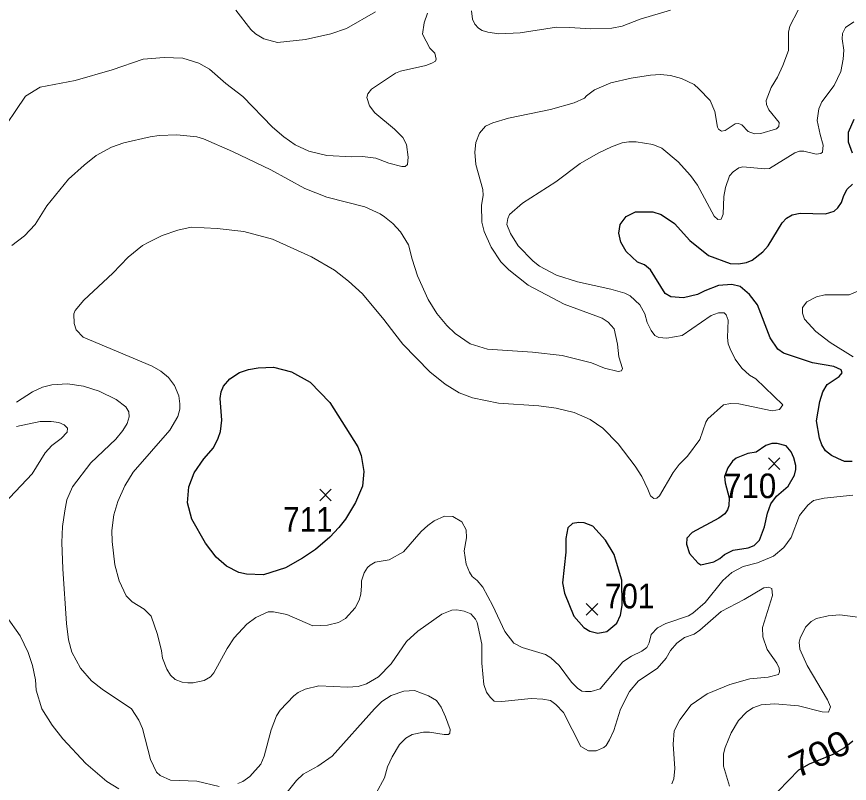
# Model space of a CAD drawing. Extents: x 294.2 to 320.3, y 7482.7 to 7510.7.
# Drawn here: x 302.381 to 305.089, y 7505.286 to 7507.777 of the extents above; entities that cross this region are included whole.
import ezdxf
from ezdxf.enums import TextEntityAlignment as Align

# ---------------------------------------------------------------- set-up
doc = ezdxf.new("R2010")
doc.units = 0
doc.header["$LTSCALE"] = 0.032
for name, color, linetype, lineweight in [('1', 7, 'Continuous', 25), ('2', 7, 'Continuous', 13), ('21', 7, 'Continuous', 25)]:
    doc.layers.add(name, color=color, linetype=linetype, lineweight=lineweight)
doc.layers.add('61', color=7, linetype='Continuous')

msp = doc.modelspace()

# ---------------------------------------------------------------- linework, layer by layer
at = {"layer": '1'}
for points in [[(305.099, 7507.3337), (305.0861, 7507.3695), (305.0861, 7507.4026), (305.1039, 7507.4448)], [(304.707, 7506.9073), (304.6637, 7506.9034), (304.6189, 7506.8868), (304.5949, 7506.8742), (304.5493, 7506.864), (304.5084, 7506.8671), (304.4903, 7506.8782), (304.4419, 7506.9553), (304.4231, 7506.971), (304.4003, 7506.9796), (304.3627, 7507.0146), (304.3454, 7507.0445), (304.3391, 7507.0736), (304.343, 7507.1019), (304.3635, 7507.1286), (304.3938, 7507.1435), (304.4496, 7507.1428), (304.4763, 7507.1349), (304.5199, 7507.1058), (304.5695, 7507.05), (304.6312, 7507.0012), (304.7012, 7506.9752), (304.7287, 7506.9744), (304.7543, 7506.9783), (304.7731, 7506.9862), (304.8077, 7507.0129), (304.8242, 7507.0326), (304.8702, 7507.1073), (304.8844, 7507.123), (304.9025, 7507.134), (304.9292, 7507.1387), (305.0106, 7507.1364), (305.0389, 7507.145), (305.0515, 7507.156), (305.0632, 7507.1741), (305.0703, 7507.1961), (305.0821, 7507.2166), (305.0986, 7507.2331)], [(304.8745, 7506.684), (304.8556, 7506.6966), (304.8312, 7506.7335), (304.7899, 7506.8413), (304.764, 7506.8751), (304.7333, 7506.901), (304.707, 7506.9073)], [(305.0976, 7506.3316), (305.0732, 7506.3324), (305.0512, 7506.3418), (305.0304, 7506.3512), (305.0115, 7506.3662), (304.9997, 7506.3866), (304.9911, 7506.4078), (304.9816, 7506.4645), (304.9923, 7506.5266), (305.0025, 7506.558), (305.0166, 7506.5824), (305.0552, 7506.6083), (305.0654, 7506.6201), (305.0619, 7506.6303), (305.0383, 7506.6405), (304.9691, 7506.6531), (304.8745, 7506.684)], [(304.8567, 7505.261), (304.9246, 7505.3302), (304.9594, 7505.3499), (305.0364, 7505.3805), (305.072, 7505.4017), (305.0995, 7505.424)]]:
    msp.add_lwpolyline(points, dxfattribs=at)
for points in [[(302.9901, 7506.3406), (303.0208, 7506.3767), (303.0369, 7506.4082), (303.0439, 7506.4295), (303.0479, 7506.4664), (303.0426, 7506.5372), (303.0461, 7506.5586), (303.054, 7506.5767), (303.0744, 7506.601), (303.1055, 7506.6207), (303.1354, 7506.6309), (303.1668, 7506.6364), (303.2166, 7506.6388), (303.2749, 7506.6237), (303.3358, 7506.5901), (303.3993, 7506.5242), (303.4905, 7506.3801), (303.5015, 7506.3518), (303.5097, 7506.2994), (303.5052, 7506.2518), (303.4832, 7506.1983), (303.4502, 7506.1448), (303.4292, 7506.1173), (303.3993, 7506.0858), (303.3529, 7506.0465), (303.3104, 7506.0174), (303.2549, 7505.9867), (303.1836, 7505.9639), (303.1285, 7505.9655), (303.1036, 7505.9718), (303.0634, 7505.9916), (303.0295, 7506.0216), (302.9951, 7506.067), (302.951, 7506.1448), (302.937, 7506.1972), (302.9414, 7506.2496), (302.9587, 7506.2955)], [(304.8543, 7506.3906), (304.8368, 7506.3906), (304.8171, 7506.3843), (304.7857, 7506.3623), (304.7589, 7506.3584), (304.7208, 7506.3426), (304.7082, 7506.3332), (304.6941, 7506.3119), (304.6831, 7506.2836), (304.6854, 7506.263), (304.698, 7506.2142), (304.6969, 7506.1878), (304.6922, 7506.1752), (304.6835, 7506.1619), (304.6638, 7506.1477), (304.5779, 7506.1013), (304.5606, 7506.0824), (304.559, 7506.0636), (304.5689, 7506.0331), (304.5957, 7506.0031), (304.6059, 7505.9967), (304.6477, 7506.0062), (304.6674, 7506.0164), (304.6823, 7506.0298), (304.7113, 7506.044), (304.7598, 7506.0516), (304.779, 7506.0593), (304.7962, 7506.0765), (304.8128, 7506.1193), (304.8224, 7506.164), (304.8332, 7506.1947), (304.8517, 7506.2195), (304.8894, 7506.2514), (304.9098, 7506.2879), (304.9143, 7506.3058), (304.915, 7506.3185), (304.9086, 7506.3434), (304.899, 7506.3632), (304.883, 7506.383)], [(304.332, 7506.0043), (304.3236, 7506.0295), (304.2959, 7506.0767), (304.2543, 7506.1215), (304.2268, 7506.1325), (304.2087, 7506.1333), (304.1882, 7506.1301), (304.1733, 7506.1168), (304.167, 7506.0822), (304.167, 7506.0374), (304.1558, 7505.9374), (304.1629, 7505.9044), (304.1923, 7505.8289), (304.2249, 7505.7927), (304.2446, 7505.7809), (304.2713, 7505.7746), (304.2996, 7505.7801), (304.3327, 7505.8069), (304.3447, 7505.8328), (304.3498, 7505.8643), (304.3491, 7505.9469)]]:
    msp.add_lwpolyline(points, close=True, dxfattribs=at)
at = {"layer": '2'}
for points in [[(302.9734, 7507.6268), (303.0079, 7507.607), (303.0608, 7507.5597), (303.117, 7507.5175), (303.2134, 7507.4179), (303.2498, 7507.3867), (303.2862, 7507.3605), (303.3309, 7507.3401), (303.3897, 7507.326), (303.4714, 7507.3222), (303.5059, 7507.3235), (303.5493, 7507.3171), (303.5914, 7507.3017), (303.6336, 7507.2909), (303.6444, 7507.2909), (303.6521, 7507.2966), (303.6539, 7507.3209), (303.6482, 7507.3624), (303.6367, 7507.3848), (303.6099, 7507.4122), (303.5454, 7507.4652), (303.5282, 7507.4882), (303.5199, 7507.515), (303.5231, 7507.5271), (303.5346, 7507.5418), (303.6131, 7507.5936), (303.6297, 7507.6), (303.7115, 7507.6191), (303.7314, 7507.626), (303.7427, 7507.6331), (303.7453, 7507.6389), (303.7408, 7507.6587), (303.7249, 7507.6746), (303.7006, 7507.7206), (303.7057, 7507.7577), (303.7172, 7507.7883)], [(303.548, 7507.7928), (303.4535, 7507.7385), (303.4024, 7507.7213), (303.3207, 7507.7027), (303.2288, 7507.6938), (303.1853, 7507.7053), (303.1579, 7507.7219), (303.1426, 7507.7359), (303.0934, 7507.7985)], [(304.507, 7507.7985), (304.4087, 7507.7691), (304.3499, 7507.7461), (304.3167, 7507.7397), (304.2478, 7507.7379), (304.1788, 7507.7423), (304.1367, 7507.7436), (304.0179, 7507.7244), (303.949, 7507.7219), (303.9132, 7507.727), (303.8953, 7507.7321), (303.8825, 7507.7397), (303.871, 7507.7526), (303.8628, 7507.7692), (303.8602, 7507.796)], [(304.2272, 7507.5125), (304.2335, 7507.5203), (304.2605, 7507.5392), (304.3134, 7507.5626), (304.3793, 7507.5776), (304.4419, 7507.5878), (304.4751, 7507.5897), (304.507, 7507.5859), (304.5428, 7507.577), (304.5836, 7507.5571), (304.5996, 7507.5431), (304.6366, 7507.5048), (304.6512, 7507.4691), (304.6596, 7507.418), (304.663, 7507.4116), (304.673, 7507.4052), (304.6851, 7507.4071), (304.7177, 7507.4288), (304.7278, 7507.4301), (304.7388, 7507.4263), (304.7598, 7507.4045), (304.7803, 7507.3962), (304.8006, 7507.3981), (304.8516, 7507.4131), (304.8593, 7507.4207), (304.86, 7507.4338), (304.8269, 7507.4742), (304.8198, 7507.4921), (304.8185, 7507.5048), (304.8341, 7507.5474), (304.8547, 7507.5813), (304.8725, 7507.6189), (304.8903, 7507.6673), (304.8913, 7507.727), (304.8951, 7507.7462), (304.9226, 7507.7985)], [(305.1033, 7507.7608), (305.0765, 7507.7417), (305.0663, 7507.7232), (305.065, 7507.7053), (305.0708, 7507.6683), (305.0688, 7507.6389), (305.0612, 7507.5993), (305.0395, 7507.5533), (304.9993, 7507.5003), (304.989, 7507.478), (304.9839, 7507.4397), (304.9935, 7507.395), (305.0031, 7507.3599)], [(302.4575, 7507.5482), (302.5711, 7507.5699), (302.6912, 7507.6044), (302.7921, 7507.6389), (302.861, 7507.6452), (302.921, 7507.6427), (302.9734, 7507.6268)], [(302.317, 7507.3829), (302.4096, 7507.5195), (302.4575, 7507.5482)], [(303.8858, 7507.3988), (303.9055, 7507.4218), (303.9298, 7507.4327), (303.9809, 7507.448), (304.1175, 7507.4761), (304.1941, 7507.4971), (304.2272, 7507.5125)], [(302.3652, 7507.034), (302.4066, 7507.0652), (302.4416, 7507.1017), (302.4798, 7507.1626), (302.5501, 7507.2494), (302.6005, 7507.2954), (302.6394, 7507.326), (302.6899, 7507.3535), (302.7295, 7507.3675), (302.815, 7507.3867), (302.8444, 7507.3911), (302.9019, 7507.3937), (302.967, 7507.3867), (302.9887, 7507.3809), (303.0832, 7507.3388), (303.2071, 7507.28), (303.3182, 7507.2194), (303.3897, 7507.1906), (303.5135, 7507.1594), (303.5633, 7507.1364), (303.5773, 7507.1268), (303.6041, 7507.1051), (303.6297, 7507.0783), (303.6552, 7507.0355), (303.6667, 7506.9889), (303.6846, 7506.9353), (303.7191, 7506.8587), (303.7478, 7506.8127), (303.7798, 7506.7738), (303.8066, 7506.7482), (303.8557, 7506.7143), (303.9119, 7506.6965), (304.0588, 7506.6875), (304.1546, 7506.676), (304.2503, 7506.6525), (304.2925, 7506.6358), (304.3372, 7506.6244), (304.3474, 7506.6269), (304.3506, 7506.6339), (304.3391, 7506.6722), (304.3346, 7506.7131), (304.3237, 7506.7629), (304.3048, 7506.7844), (304.2853, 7506.7972), (304.1618, 7506.8432), (304.0447, 7506.9046), (303.9815, 7506.9551), (303.956, 7506.9813), (303.9241, 7507.0285), (303.9017, 7507.0796), (303.894, 7507.1102), (303.8927, 7507.1652), (303.8978, 7507.1958), (303.8972, 7507.2162), (303.8743, 7507.2967), (303.8704, 7507.3375), (303.8743, 7507.3682), (303.8858, 7507.3988)], [(304.9118, 7507.335), (304.8288, 7507.2845), (304.8135, 7507.2826), (304.7419, 7507.2897), (304.7298, 7507.2858), (304.7107, 7507.2737), (304.6992, 7507.2597), (304.6864, 7507.2226), (304.6806, 7507.1932), (304.6787, 7507.1358), (304.6717, 7507.1191), (304.6615, 7507.1185), (304.6487, 7507.1287), (304.5945, 7507.2303), (304.5721, 7507.2609), (304.5325, 7507.3056), (304.4795, 7507.3503), (304.4495, 7507.3618), (304.3959, 7507.3707), (304.3716, 7507.3707), (304.3499, 7507.3669), (304.3155, 7507.3548), (304.272, 7507.3343), (304.2133, 7507.2999), (304.1348, 7507.2411), (304.0256, 7507.1715), (303.9841, 7507.1351), (303.9783, 7507.1217), (303.9751, 7507.1019), (303.9866, 7507.0732), (304.0115, 7507.033), (304.0607, 7506.9825), (304.0811, 7506.9672), (304.1365, 7506.9377), (304.2043, 7506.9155), (304.3129, 7506.8918), (304.3589, 7506.8785), (304.3755, 7506.8708), (304.4074, 7506.8408), (304.4234, 7506.8114), (304.4316, 7506.7833), (304.4444, 7506.7578), (304.4565, 7506.7418), (304.4687, 7506.7348), (304.4955, 7506.7322), (304.5453, 7506.7418), (304.6398, 7506.8063), (304.6633, 7506.8155), (304.6817, 7506.8155), (304.688, 7506.8089), (304.6943, 7506.791), (304.6926, 7506.7348), (304.6949, 7506.7142), (304.7011, 7506.6978), (304.7177, 7506.6646), (304.7387, 7506.6352), (304.7643, 7506.6122), (304.7841, 7506.6001), (304.8722, 7506.5165), (304.8613, 7506.5011), (304.8377, 7506.4967), (304.7292, 7506.5196), (304.7024, 7506.5209), (304.6793, 7506.5158), (304.6289, 7506.4705), (304.6221, 7506.4602), (304.6025, 7506.404), (304.5623, 7506.3491), (304.5348, 7506.3218), (304.5153, 7506.2962), (304.4712, 7506.2202), (304.4623, 7506.2125), (304.4527, 7506.2119), (304.4425, 7506.2208), (304.4329, 7506.2419), (304.4137, 7506.2828), (304.3927, 7506.3173), (304.3365, 7506.3894), (304.2873, 7506.4398), (304.2458, 7506.4686), (304.1941, 7506.4909), (304.1354, 7506.5049), (304.0792, 7506.5126), (303.948, 7506.5219), (303.8634, 7506.5394), (303.82, 7506.5554), (303.7746, 7506.5835), (303.7248, 7506.6237), (303.6373, 7506.7131), (303.6105, 7506.7463), (303.5755, 7506.7936), (303.5052, 7506.8772), (303.4599, 7506.9181), (303.4145, 7506.9538), (303.3401, 7506.9965)], [(305.0031, 7507.3599), (305.0018, 7507.3375), (304.9961, 7507.333), (304.9813, 7507.3305), (304.9412, 7507.3401), (304.9265, 7507.3407), (304.9118, 7507.335)], [(303.3401, 7506.9965), (303.2132, 7507.0547), (303.1202, 7507.0796), (303.0334, 7507.0892), (302.9491, 7507.0936), (302.9057, 7507.0834), (302.8546, 7507.0662)], [(302.8546, 7507.0662), (302.8112, 7507.0451), (302.7899, 7507.0343), (302.7434, 7506.9964), (302.6937, 7506.9436), (302.5992, 7506.8561), (302.5711, 7506.8229), (302.5667, 7506.8114), (302.5685, 7506.7808), (302.5749, 7506.7597), (302.5979, 7506.7361), (302.8214, 7506.6422), (302.8495, 7506.6256), (302.8744, 7506.6046), (302.8948, 7506.579), (302.9089, 7506.5458), (302.9114, 7506.519), (302.9114, 7506.5024), (302.9051, 7506.4782), (302.8789, 7506.4335), (302.7601, 7506.2968), (302.7327, 7506.2534), (302.7103, 7506.2023), (302.6969, 7506.1589), (302.6911, 7506.1078), (302.6918, 7506.0721), (302.7007, 7505.9967), (302.7141, 7505.9444), (302.7371, 7505.8952), (302.7569, 7505.8761), (302.7959, 7505.8518), (302.8182, 7505.8294), (302.8393, 7505.7694), (302.852, 7505.7171), (302.8559, 7505.6928), (302.8693, 7505.6571), (302.8814, 7505.6379), (302.8961, 7505.6239), (302.9197, 7505.6149), (302.9376, 7505.6123), (302.9555, 7505.6123), (302.9913, 7505.62), (303.011, 7505.6328), (303.0219, 7505.6456), (303.0653, 7505.7248), (303.0883, 7505.7592), (303.1298, 7505.8032), (303.1585, 7505.825), (303.1994, 7505.8435), (303.216, 7505.8435), (303.2594, 7505.8345), (303.3437, 7505.7982), (303.3922, 7505.8), (303.428, 7505.809), (303.4503, 7505.8218), (303.4816, 7505.8563), (303.495, 7505.8818), (303.5007, 7505.901), (303.502, 7505.9278), (303.5027, 7505.9444), (303.5109, 7505.9699), (303.5218, 7505.9871), (303.5307, 7505.9948), (303.5467, 7506.0044), (303.5927, 7506.0127), (303.6387, 7506.0389), (303.6968, 7506.104), (303.7178, 7506.1244), (303.7383, 7506.1391), (303.7728, 7506.1544), (303.7996, 7506.1538), (303.8289, 7506.1359), (303.8423, 7506.1104), (303.8442, 7506.0836), (303.8366, 7506.0414), (303.8429, 7505.998), (303.8532, 7505.9725), (303.8621, 7505.9578), (303.8787, 7505.945), (303.8972, 7505.924), (303.9292, 7505.8627), (303.9688, 7505.7797), (303.9981, 7505.742), (304.0243, 7505.7279), (304.1003, 7505.705), (304.1182, 7505.6941), (304.145, 7505.6692), (304.1852, 7505.6149), (304.2043, 7505.5951), (304.2184, 7505.5855), (304.2312, 7505.5842), (304.2491, 7505.5842), (304.2784, 7505.5938), (304.3525, 7505.6807), (304.3806, 7505.6998)], [(305.1008, 7506.6716), (305.0267, 7506.7182), (304.9801, 7506.7546), (304.943, 7506.7948), (304.936, 7506.814), (304.936, 7506.8325), (304.9507, 7506.851), (304.982, 7506.867), (305.0088, 7506.8734), (305.088, 7506.874), (305.1212, 7506.8874)], [(302.5315, 7505.9827), (302.5284, 7506.0683), (302.5302, 7506.1206), (302.5373, 7506.1717), (302.5443, 7506.2074), (302.5622, 7506.2496), (302.6228, 7506.3275), (302.7039, 7506.4047), (302.7262, 7506.4328), (302.7409, 7506.4552), (302.7467, 7506.4769), (302.746, 7506.4935), (302.7365, 7506.5094), (302.7045, 7506.5337), (302.649, 7506.5605), (302.598, 7506.5764), (302.5469, 7506.5841), (302.4958, 7506.5815), (302.4652, 7506.5733), (302.4326, 7506.5586), (302.3802, 7506.5247)], [(302.3406, 7506.1959), (302.4313, 7506.2917), (302.4734, 7506.36), (302.4958, 7506.3843), (302.5258, 7506.4066), (302.545, 7506.4271), (302.5468, 7506.4404), (302.536, 7506.4513), (302.5188, 7506.4583), (302.4932, 7506.4622), (302.4575, 7506.4615), (302.3809, 7506.4462)], [(304.4917, 7505.8052), (304.5657, 7505.8301), (304.5798, 7505.839), (304.62, 7505.8735), (304.6775, 7505.945), (304.7068, 7505.9718), (304.7432, 7505.9903), (304.7905, 7506.0031), (304.8416, 7506.0248), (304.876, 7506.0523), (304.899, 7506.0849), (304.9265, 7506.1564), (304.9533, 7506.1902), (304.9718, 7506.2049), (305.0063, 7506.2132), (305.0995, 7506.2227)], [(302.6592, 7505.5926), (302.6241, 7505.6194), (302.5884, 7505.6609), (302.5603, 7505.712), (302.5501, 7505.7528), (302.5437, 7505.8052), (302.5315, 7505.9827)], [(304.5115, 7505.2842), (304.5178, 7505.3014), (304.521, 7505.334), (304.5159, 7505.4132), (304.5191, 7505.4566), (304.537, 7505.4923), (304.5746, 7505.5415), (304.6268, 7505.5774), (304.7004, 7505.6079), (304.7649, 7505.6258), (304.825, 7505.6315), (304.8581, 7505.6398), (304.8613, 7505.6481), (304.8601, 7505.6609), (304.8531, 7505.6769), (304.8211, 7505.7209), (304.807, 7505.7618), (304.8064, 7505.7924), (304.8384, 7505.8971), (304.8371, 7505.9188), (304.8262, 7505.9233), (304.8109, 7505.9214), (304.747, 7505.8837), (304.6717, 7505.8448), (304.6028, 7505.7835), (304.5836, 7505.7707), (304.553, 7505.7599), (304.5274, 7505.742), (304.507, 7505.7183), (304.4929, 7505.6928), (304.4635, 7505.6596), (304.4029, 7505.6194), (304.3736, 7505.5843), (304.3442, 7505.5268), (304.3225, 7505.4579), (304.309, 7505.4272), (304.2982, 7505.4093), (304.2905, 7505.4023), (304.265, 7505.3914), (304.2401, 7505.3921), (304.2152, 7505.4055), (304.159, 7505.5166), (304.1341, 7505.5428), (304.1175, 7505.5549), (304.092, 7505.56), (304.0537, 7505.5619), (303.9592, 7505.5523), (303.9336, 7505.5536), (303.9208, 7505.5658), (303.9093, 7505.583), (303.9004, 7505.6073), (303.8934, 7505.6762), (303.894, 7505.7388), (303.8781, 7505.809), (303.8736, 7505.8198), (303.8583, 7505.8365), (303.8366, 7505.8454), (303.8123, 7505.8505), (303.7957, 7505.8486), (303.7631, 7505.8358), (303.6859, 7505.7809), (303.6489, 7505.7471), (303.599, 7505.6749), (303.5576, 7505.6328), (303.5186, 7505.6092), (303.4918, 7505.6008), (303.4573, 7505.5983), (303.3641, 7505.6034), (303.3194, 7505.5926), (303.2964, 7505.5811), (303.2824, 7505.5702), (303.2377, 7505.5243), (303.2262, 7505.5051), (303.209, 7505.4604), (303.186, 7505.3749), (303.1751, 7505.3481), (303.1394, 7505.3084), (303.1164, 7505.2925), (303.0998, 7505.2854)], [(305.1161, 7505.8263), (305.0574, 7505.8339), (305.0203, 7505.8301), (304.982, 7505.8218), (304.9641, 7505.8122), (304.9456, 7505.7937), (304.9284, 7505.758), (304.9258, 7505.7452), (304.9277, 7505.7222), (304.952, 7505.6686), (305.0178, 7505.5575), (305.0274, 7505.5351), (305.021, 7505.5178), (304.9999, 7505.5191), (304.9233, 7505.5383), (304.8467, 7505.5441), (304.8018, 7505.5408), (304.7753, 7505.5313), (304.7547, 7505.5179), (304.7283, 7505.4906), (304.7047, 7505.45), (304.6845, 7505.403), (304.6793, 7505.3825), (304.6793, 7505.3417), (304.6992, 7505.2772)], [(302.7135, 7505.2688), (302.6746, 7505.2925), (302.6056, 7505.3512), (302.5315, 7505.431), (302.497, 7505.4751), (302.4632, 7505.5281), (302.4441, 7505.5894), (302.4421, 7505.6226), (302.4326, 7505.6686), (302.4187, 7505.7118), (302.393, 7505.765), (302.3483, 7505.8282)], [(304.3806, 7505.6998), (304.4144, 7505.7158), (304.4297, 7505.7279), (304.4374, 7505.7426), (304.4444, 7505.7694), (304.4649, 7505.7911), (304.4917, 7505.8052)], [(303.0398, 7505.2759), (302.967, 7505.2931), (302.8814, 7505.2969), (302.8482, 7505.3117), (302.8354, 7505.3225), (302.8163, 7505.3634), (302.7901, 7505.4643), (302.7786, 7505.4911), (302.755, 7505.5287), (302.6592, 7505.5926)], [(303.5505, 7505.2548), (303.5767, 7505.3046), (303.5875, 7505.3404), (303.6016, 7505.3723), (303.6265, 7505.4125), (303.647, 7505.433), (303.6667, 7505.4445), (303.7038, 7505.4527), (303.723, 7505.4527), (303.7715, 7505.4451), (303.7855, 7505.4451), (303.7893, 7505.4496), (303.7906, 7505.4617), (303.7753, 7505.5026), (303.7619, 7505.5332), (303.7466, 7505.5555), (303.7204, 7505.5709), (303.6744, 7505.5875), (303.6399, 7505.5855), (303.5991, 7505.5715)], [(303.5991, 7505.5715), (303.569, 7505.5517), (303.5442, 7505.5287), (303.4075, 7505.3748), (303.3603, 7505.3423), (303.3124, 7505.3155), (303.2913, 7505.295)], [(303.2913, 7505.295), (303.2389, 7505.2305)]]:
    msp.add_lwpolyline(points, dxfattribs=at)
at = {"layer": '21'}
for p, q in [((304.8256, 7506.3437), (304.8631, 7506.3062)), ((304.8631, 7506.3437), (304.8256, 7506.3062)), ((303.3668, 7506.2419), (303.4043, 7506.2044)), ((303.4043, 7506.2419), (303.3668, 7506.2044)), ((304.2334, 7505.8707), (304.2709, 7505.8332)), ((304.2709, 7505.8707), (304.2334, 7505.8332))]:
    msp.add_line(p, q, dxfattribs=at)

# ---------------------------------------------------------------- texts
at = {"layer": '61'}
for s, width, p in [('710', 0.95, (304.7662, 7506.2129)), ('711', 0.9, (303.3281, 7506.1038)), ('701', 0.9, (304.3741, 7505.8548))]:
    msp.add_text(s, height=0.08, dxfattribs=dict(at, width=width)).set_placement(p, align=Align.CENTER)
at = {"layer": '61', "width": 1.15}
msp.add_text('700', height=0.08, rotation=26.565, dxfattribs=at).set_placement((305.0096, 7505.3465), align=Align.CENTER)

doc.saveas('drawing.dxf')
